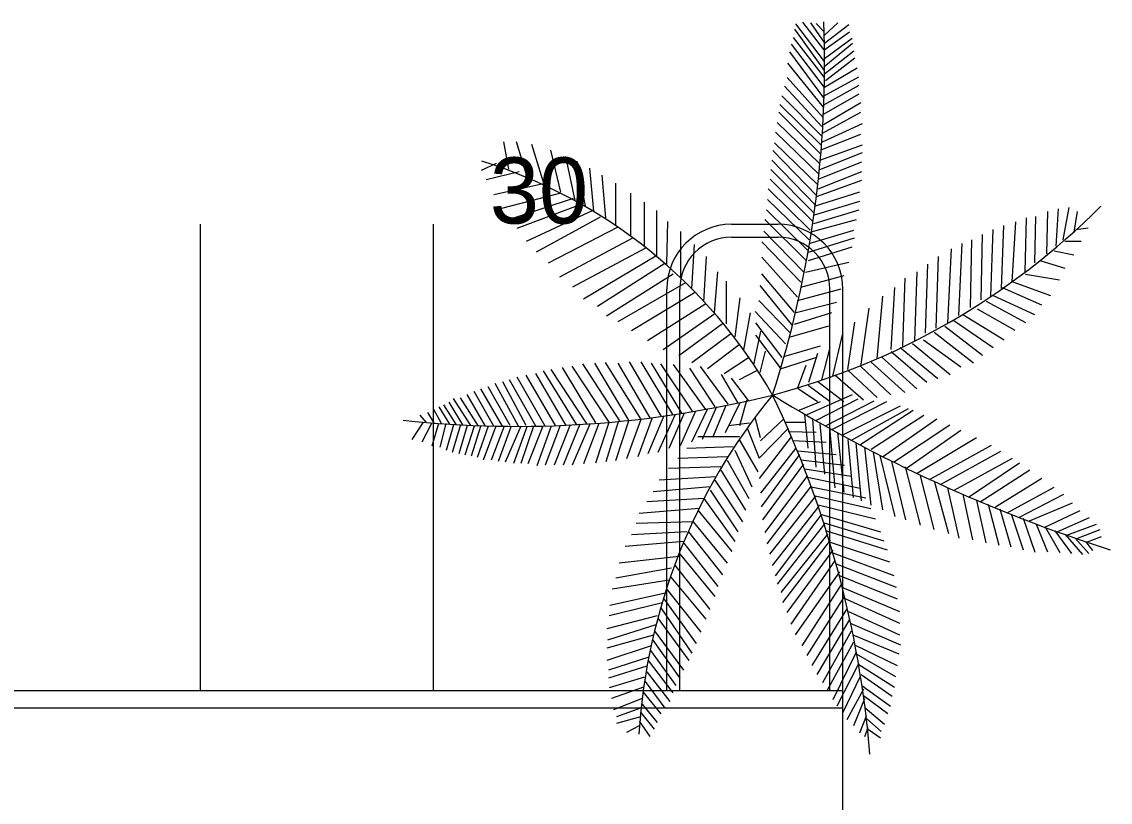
# Model space of a CAD drawing. Extents: x 6711323 to 6714641, y 1869258 to 1871224.
# Drawn here: x 6712869.21 to 6712911.22, y 1869741.77 to 1869771.88 of the extents above; entities that cross this region are included whole.
import ezdxf

# ---------------------------------------------------------------- set-up
doc = ezdxf.new("R2010")
doc.units = 0
for name, color, linetype in [('Curb Gutter (21)', 7, 'Continuous'), ('Exist Veg_Nat(4)', 7, 'Continuous'), ('Front Align (17)', 7, 'Continuous'), ('Ramp Anno (14)', 7, 'Continuous')]:
    doc.layers.add(name, color=color, linetype=linetype)

msp = doc.modelspace()

# ---------------------------------------------------------------- linework, layer by layer
at = {"layer": 'Curb Gutter (21)'}
for p, q in [((6712896.607, 1869764.072), (6712898.399, 1869764.072)), ((6712896.607, 1869763.572), (6712898.399, 1869763.572)), ((6712894.107, 1869746.072), (6712894.107, 1869761.572)), ((6712894.607, 1869746.072), (6712894.607, 1869761.572)), ((6712900.399, 1869746.097), (6712900.399, 1869761.572)), ((6712900.899, 1869712.572), (6712900.899, 1869761.572)), ((6712900.899, 1869746.072), (6712840.54, 1869746.072)), ((6712900.899, 1869745.406), (6712840.54, 1869745.406))]:
    msp.add_line(p, q, dxfattribs=at)
for centre, radius, start, end in [((6712896.607, 1869761.572), 2.5, 90, 180), ((6712898.399, 1869761.572), 2.5, 360, 90), ((6712896.607, 1869761.572), 2, 90, 180), ((6712898.399, 1869761.572), 2, 360, 90)]:
    msp.add_arc(centre, radius, start, end, dxfattribs=at)
at = {"layer": 'Exist Veg_Nat(4)'}
for p, q in [((6712900.192, 1869770.353), (6712899.084, 1869771.799)), ((6712900.171, 1869770.812), (6712899.361, 1869771.868)), ((6712900.192, 1869771.087), (6712899.659, 1869771.845)), ((6712900.149, 1869771.524), (6712899.873, 1869771.822)), ((6712900.192, 1869771.363), (6712900.703, 1869771.845)), ((6712900.192, 1869771.064), (6712901.129, 1869771.776)), ((6712900.192, 1869769.733), (6712898.999, 1869771.271)), ((6712900.192, 1869770.008), (6712899.042, 1869771.592)), ((6712900.171, 1869770.789), (6712901.151, 1869771.501)), ((6712900.192, 1869770.468), (6712901.257, 1869771.248)), ((6712900.192, 1869769.343), (6712898.914, 1869771.019)), ((6712900.171, 1869770.146), (6712901.278, 1869771.064)), ((6712900.171, 1869768.953), (6712898.85, 1869770.72)), ((6712900.192, 1869769.871), (6712901.321, 1869770.766)), ((6712900.235, 1869769.618), (6712901.364, 1869770.491)), ((6712900.153, 1869768.584), (6712898.779, 1869770.286)), ((6712900.192, 1869769.366), (6712901.449, 1869770.101)), ((6712900.118, 1869768.214), (6712898.745, 1869769.731)), ((6712900.128, 1869768.998), (6712901.513, 1869769.756)), ((6712900.084, 1869767.844), (6712898.642, 1869769.398)), ((6712900.171, 1869768.677), (6712901.534, 1869769.435)), ((6712900.084, 1869767.473), (6712898.539, 1869769.028)), ((6712900.153, 1869768.325), (6712901.526, 1869769.102)), ((6712900.153, 1869767.917), (6712901.595, 1869768.769)), ((6712900.05, 1869766.77), (6712898.436, 1869768.399)), ((6712900.05, 1869767.14), (6712898.47, 1869768.695)), ((6712900.118, 1869767.584), (6712901.595, 1869768.399)), ((6712900.015, 1869766.4), (6712898.367, 1869767.992)), ((6712900.118, 1869767.252), (6712901.664, 1869767.955)), ((6712899.981, 1869765.993), (6712898.298, 1869767.622)), ((6712900.084, 1869766.955), (6712901.595, 1869767.548)), ((6712888.015, 1869766.2), (6712887.82, 1869767.251)), ((6712888.698, 1869765.937), (6712888.307, 1869767.251)), ((6712889.381, 1869765.569), (6712888.893, 1869767.146)), ((6712899.947, 1869765.586), (6712898.264, 1869767.214)), ((6712900.015, 1869766.548), (6712901.664, 1869767.14)), ((6712890.015, 1869765.306), (6712889.625, 1869766.936)), ((6712890.57, 1869764.985), (6712890.212, 1869766.685)), ((6712899.878, 1869765.179), (6712898.195, 1869766.918)), ((6712900.015, 1869766.178), (6712901.664, 1869766.844)), ((6712887.527, 1869766.41), (6712886.941, 1869766.147)), ((6712890.963, 1869764.773), (6712890.641, 1869766.511)), ((6712891.284, 1869764.579), (6712891.141, 1869766.241)), ((6712899.844, 1869764.809), (6712898.161, 1869766.548)), ((6712899.947, 1869765.808), (6712901.629, 1869766.474)), ((6712888.405, 1869766.095), (6712887.137, 1869765.779)), ((6712891.749, 1869764.309), (6712891.606, 1869765.97)), ((6712899.741, 1869764.18), (6712898.092, 1869765.808)), ((6712899.775, 1869764.513), (6712898.127, 1869766.178)), ((6712899.947, 1869765.438), (6712901.629, 1869766.104)), ((6712889.283, 1869765.621), (6712887.429, 1869765.201)), ((6712892.142, 1869764.038), (6712892.142, 1869765.661)), ((6712899.638, 1869763.847), (6712898.024, 1869765.438)), ((6712899.878, 1869765.142), (6712901.629, 1869765.771)), ((6712889.966, 1869765.253), (6712887.722, 1869764.675)), ((6712890.498, 1869765.062), (6712888.032, 1869764.251)), ((6712892.714, 1869763.613), (6712892.714, 1869765.275)), ((6712899.603, 1869763.477), (6712897.989, 1869765.031)), ((6712899.809, 1869764.772), (6712901.561, 1869765.327)), ((6712899.809, 1869764.439), (6712901.561, 1869764.957)), ((6712890.784, 1869764.83), (6712888.318, 1869763.903)), ((6712891.249, 1869764.599), (6712888.676, 1869763.401)), ((6712893.25, 1869763.227), (6712893.25, 1869764.927)), ((6712893.715, 1869762.822), (6712893.715, 1869764.599)), ((6712899.535, 1869763.07), (6712897.955, 1869764.624)), ((6712899.775, 1869764.106), (6712901.526, 1869764.624)), ((6712908.767, 1869762.931), (6712908.812, 1869764.563)), ((6712909.134, 1869763.228), (6712909.226, 1869764.662)), ((6712909.409, 1869763.475), (6712909.639, 1869764.712)), ((6712909.822, 1869763.772), (6712909.96, 1869764.563)), ((6712891.535, 1869764.348), (6712889.069, 1869762.996)), ((6712894.108, 1869762.551), (6712894.144, 1869764.174)), ((6712899.5, 1869762.663), (6712897.887, 1869764.254)), ((6712899.672, 1869763.773), (6712901.423, 1869764.254)), ((6712907.436, 1869761.844), (6712907.574, 1869764.168)), ((6712907.941, 1869762.239), (6712907.987, 1869764.316)), ((6712908.308, 1869762.585), (6712908.354, 1869764.365)), ((6712892.214, 1869763.961), (6712889.533, 1869762.571)), ((6712894.644, 1869762.01), (6712894.644, 1869763.788)), ((6712899.397, 1869762.219), (6712897.852, 1869763.81)), ((6712899.603, 1869763.329), (6712901.32, 1869763.847)), ((6712906.61, 1869761.3), (6712906.702, 1869763.871)), ((6712907.023, 1869761.596), (6712907.115, 1869764.019)), ((6712909.886, 1869763.863), (6712910.37, 1869763.937)), ((6712892.786, 1869763.536), (6712889.962, 1869762.03)), ((6712895.073, 1869761.585), (6712895.18, 1869763.285)), ((6712899.275, 1869761.837), (6712897.775, 1869763.389)), ((6712899.569, 1869762.996), (6712901.355, 1869763.551)), ((6712905.371, 1869760.558), (6712905.509, 1869763.327)), ((6712905.83, 1869760.855), (6712905.876, 1869763.475)), ((6712906.243, 1869761.151), (6712906.289, 1869763.673)), ((6712909.471, 1869763.416), (6712910.093, 1869763.416)), ((6712893.286, 1869763.15), (6712890.463, 1869761.643)), ((6712893.679, 1869762.841), (6712890.891, 1869761.18)), ((6712899.575, 1869762.678), (6712901.255, 1869763.195)), ((6712904.958, 1869760.261), (6712905.096, 1869763.129)), ((6712909.056, 1869763.043), (6712909.817, 1869762.894)), ((6712891.428, 1869760.909), (6712894.036, 1869762.571)), ((6712895.537, 1869761.083), (6712895.644, 1869762.822)), ((6712899.155, 1869761.255), (6712897.775, 1869762.807)), ((6712899.455, 1869762.225), (6712901.135, 1869762.613)), ((6712904.086, 1869759.866), (6712904.178, 1869762.536)), ((6712904.499, 1869760.063), (6712904.591, 1869762.833)), ((6712908.503, 1869762.67), (6712909.471, 1869762.373)), ((6712891.785, 1869760.542), (6712894.358, 1869762.165)), ((6712895.947, 1869760.659), (6712896.079, 1869762.234)), ((6712899.035, 1869760.673), (6712897.775, 1869762.16)), ((6712899.275, 1869761.643), (6712900.955, 1869762.096)), ((6712903.673, 1869759.569), (6712903.765, 1869762.239)), ((6712907.95, 1869762.149), (6712909.263, 1869761.925)), ((6712894.822, 1869761.817), (6712892.214, 1869760.31)), ((6712896.41, 1869760.229), (6712896.41, 1869761.876)), ((6712898.975, 1869760.156), (6712897.715, 1869761.708)), ((6712899.155, 1869761.126), (6712900.835, 1869761.578)), ((6712902.764, 1869759.243), (6712902.902, 1869761.627)), ((6712903.215, 1869759.371), (6712903.306, 1869761.992)), ((6712907.051, 1869761.627), (6712908.572, 1869760.957)), ((6712907.465, 1869761.851), (6712908.918, 1869761.329)), ((6712895.18, 1869761.431), (6712892.749, 1869759.963)), ((6712896.742, 1869759.728), (6712896.941, 1869761.231)), ((6712902.23, 1869758.895), (6712902.441, 1869761.292)), ((6712906.705, 1869761.329), (6712908.295, 1869760.584)), ((6712895.609, 1869761.006), (6712893.357, 1869759.576)), ((6712898.855, 1869759.897), (6712897.655, 1869761.126)), ((6712899.095, 1869760.673), (6712900.655, 1869761.061)), ((6712901.596, 1869758.58), (6712901.913, 1869760.835)), ((6712906.083, 1869760.808), (6712907.535, 1869759.988)), ((6712906.429, 1869761.106), (6712907.95, 1869760.286)), ((6712895.966, 1869760.62), (6712893.965, 1869759.229)), ((6712897.073, 1869759.226), (6712897.338, 1869760.659)), ((6712898.681, 1869759.456), (6712897.521, 1869760.707)), ((6712899.035, 1869760.221), (6712900.475, 1869760.673)), ((6712905.184, 1869760.361), (6712906.705, 1869759.317)), ((6712905.53, 1869760.584), (6712907.12, 1869759.616)), ((6712896.252, 1869760.233), (6712894.572, 1869758.997)), ((6712897.471, 1869758.653), (6712897.735, 1869759.942)), ((6712898.562, 1869758.931), (6712897.545, 1869760.264)), ((6712898.875, 1869759.734), (6712900.358, 1869760.151)), ((6712901.094, 1869758.466), (6712901.358, 1869760.293)), ((6712904.423, 1869759.914), (6712905.945, 1869758.721)), ((6712904.838, 1869760.137), (6712906.29, 1869759.02)), ((6712896.573, 1869759.847), (6712895.073, 1869758.727)), ((6712898.5, 1869758.531), (6712897.545, 1869759.797)), ((6712900.513, 1869758.21), (6712900.883, 1869759.808)), ((6712904.008, 1869759.616), (6712905.46, 1869758.572)), ((6712896.895, 1869759.422), (6712895.68, 1869758.495)), ((6712897.709, 1869758.356), (6712897.918, 1869759.182)), ((6712898.617, 1869758.97), (6712900.036, 1869759.387)), ((6712899.583, 1869757.976), (6712899.929, 1869759.094)), ((6712900.091, 1869758.067), (6712900.408, 1869759.323)), ((6712902.764, 1869759.169), (6712904.147, 1869757.976)), ((6712903.109, 1869759.317), (6712904.562, 1869758.125)), ((6712903.594, 1869759.467), (6712905.046, 1869758.275)), ((6712892.292, 1869756.485), (6712890.866, 1869758.691)), ((6712892.638, 1869756.509), (6712891.326, 1869758.716)), ((6712893.098, 1869756.559), (6712891.74, 1869758.741)), ((6712893.466, 1869756.609), (6712892.223, 1869758.716)), ((6712893.903, 1869756.658), (6712892.661, 1869758.766)), ((6712894.34, 1869756.733), (6712893.121, 1869758.766)), ((6712894.685, 1869756.782), (6712893.512, 1869758.716)), ((6712895.1, 1869756.857), (6712893.88, 1869758.692)), ((6712895.606, 1869756.931), (6712894.363, 1869758.667)), ((6712897.253, 1869758.92), (6712896.323, 1869758.302)), ((6712898.5, 1869758.498), (6712899.856, 1869758.931)), ((6712901.992, 1869758.752), (6712903.286, 1869757.582)), ((6712902.388, 1869758.952), (6712903.761, 1869757.724)), ((6712889.807, 1869756.311), (6712888.68, 1869758.245)), ((6712890.221, 1869756.311), (6712889.048, 1869758.319)), ((6712890.635, 1869756.336), (6712889.347, 1869758.419)), ((6712891.027, 1869756.361), (6712889.646, 1869758.468)), ((6712891.372, 1869756.41), (6712890.083, 1869758.543)), ((6712891.878, 1869756.435), (6712890.451, 1869758.592)), ((6712895.974, 1869757.03), (6712894.992, 1869758.515)), ((6712896.48, 1869757.129), (6712895.408, 1869758.59)), ((6712896.841, 1869757.192), (6712896.215, 1869758.281)), ((6712897.574, 1869758.417), (6712896.895, 1869758.07)), ((6712899.147, 1869757.732), (6712899.486, 1869758.631)), ((6712900.593, 1869758.267), (6712901.702, 1869757.296)), ((6712901.094, 1869758.438), (6712902.23, 1869757.382)), ((6712901.596, 1869758.58), (6712902.758, 1869757.496)), ((6712888.058, 1869756.311), (6712887.207, 1869757.799)), ((6712888.38, 1869756.286), (6712887.483, 1869757.923)), ((6712888.68, 1869756.311), (6712887.782, 1869757.997)), ((6712889.048, 1869756.286), (6712888.035, 1869758.071)), ((6712889.416, 1869756.286), (6712888.334, 1869758.171)), ((6712897.257, 1869757.267), (6712896.598, 1869758.131)), ((6712899.563, 1869757.867), (6712900.408, 1869757.239)), ((6712899.933, 1869758.01), (6712900.936, 1869757.239)), ((6712886.839, 1869756.286), (6712886.148, 1869757.377)), ((6712887.115, 1869756.286), (6712886.401, 1869757.501)), ((6712887.437, 1869756.286), (6712886.677, 1869757.625)), ((6712887.759, 1869756.286), (6712886.931, 1869757.724)), ((6712899.178, 1869757.732), (6712899.918, 1869757.232)), ((6712899.517, 1869756.732), (6712901.274, 1869757.499)), ((6712885.734, 1869756.36), (6712885.32, 1869757.03)), ((6712885.987, 1869756.335), (6712885.504, 1869757.104)), ((6712886.24, 1869756.335), (6712885.711, 1869757.203)), ((6712886.539, 1869756.311), (6712885.872, 1869757.352)), ((6712895.675, 1869756.956), (6712895.054, 1869755.667)), ((6712896.02, 1869757.03), (6712895.468, 1869755.766)), ((6712896.388, 1869757.08), (6712895.894, 1869755.9)), ((6712896.91, 1869757.154), (6712896.354, 1869756.027)), ((6712897.188, 1869757.267), (6712896.91, 1869756.29)), ((6712899.209, 1869756.899), (6712900.041, 1869757.232)), ((6712899.856, 1869756.499), (6712901.489, 1869757.332)), ((6712900.226, 1869756.3), (6712902.105, 1869757.265)), ((6712900.503, 1869756.166), (6712902.599, 1869757.232)), ((6712900.873, 1869755.933), (6712903.123, 1869757.066)), ((6712901.212, 1869755.733), (6712903.431, 1869756.966)), ((6712884.814, 1869756.435), (6712884.584, 1869756.707)), ((6712885.136, 1869756.385), (6712884.883, 1869756.806)), ((6712885.412, 1869756.385), (6712885.113, 1869756.931)), ((6712893.098, 1869756.534), (6712892.546, 1869755.022)), ((6712893.535, 1869756.609), (6712892.983, 1869755.096)), ((6712893.995, 1869756.683), (6712893.374, 1869755.22)), ((6712894.432, 1869756.733), (6712893.765, 1869755.27)), ((6712894.778, 1869756.782), (6712894.179, 1869755.419)), ((6712895.215, 1869756.857), (6712894.617, 1869755.518)), ((6712897.501, 1869756.629), (6712897.709, 1869755.84)), ((6712898.628, 1869756.569), (6712897.724, 1869755.715)), ((6712899.425, 1869756.732), (6712899.548, 1869755.433)), ((6712899.733, 1869756.566), (6712899.856, 1869754.7)), ((6712901.551, 1869755.567), (6712903.615, 1869756.899)), ((6712901.991, 1869755.393), (6712904.031, 1869756.701)), ((6712902.425, 1869755.095), (6712904.528, 1869756.565)), ((6712884.698, 1869756.435), (6712884.261, 1869755.765)), ((6712885.021, 1869756.385), (6712884.653, 1869755.666)), ((6712885.297, 1869756.385), (6712885.044, 1869755.517)), ((6712885.573, 1869756.385), (6712885.343, 1869755.467)), ((6712885.872, 1869756.335), (6712885.596, 1869755.344)), ((6712886.148, 1869756.335), (6712885.826, 1869755.269)), ((6712886.401, 1869756.311), (6712886.079, 1869755.22)), ((6712886.677, 1869756.286), (6712886.309, 1869755.17)), ((6712886.931, 1869756.311), (6712886.562, 1869755.121)), ((6712887.207, 1869756.286), (6712886.793, 1869755.071)), ((6712887.506, 1869756.286), (6712887.023, 1869754.972)), ((6712887.828, 1869756.286), (6712887.322, 1869754.972)), ((6712888.104, 1869756.286), (6712887.598, 1869754.922)), ((6712888.473, 1869756.286), (6712887.874, 1869754.898)), ((6712888.703, 1869756.261), (6712888.196, 1869754.848)), ((6712888.956, 1869756.286), (6712888.473, 1869754.848)), ((6712889.324, 1869756.286), (6712888.749, 1869754.823)), ((6712889.646, 1869756.286), (6712889.094, 1869754.749)), ((6712889.991, 1869756.311), (6712889.416, 1869754.773)), ((6712890.382, 1869756.336), (6712889.761, 1869754.773)), ((6712890.75, 1869756.361), (6712890.106, 1869754.774)), ((6712891.141, 1869756.361), (6712890.451, 1869754.774)), ((6712891.487, 1869756.385), (6712890.889, 1869754.823)), ((6712891.372, 1869754.873), (6712891.878, 1869756.435)), ((6712891.763, 1869754.923), (6712892.246, 1869756.46)), ((6712892.638, 1869756.509), (6712892.131, 1869754.947)), ((6712897.292, 1869756.403), (6712896.493, 1869756.29)), ((6712897.223, 1869756.178), (6712897.674, 1869755.051)), ((6712898.798, 1869756.203), (6712897.667, 1869755.045)), ((6712898.685, 1869756.437), (6712899.454, 1869756.437)), ((6712900.01, 1869756.366), (6712900.195, 1869754.434)), ((6712900.38, 1869756.233), (6712900.596, 1869753.901)), ((6712902.855, 1869754.891), (6712905.03, 1869756.335)), ((6712903.356, 1869754.661), (6712905.46, 1869756.131)), ((6712896.908, 1869755.87), (6712895.301, 1869755.87)), ((6712896.908, 1869755.741), (6712897.623, 1869754.522)), ((6712898.905, 1869755.872), (6712897.667, 1869754.267)), ((6712898.794, 1869756.08), (6712899.867, 1869756.051)), ((6712898.959, 1869755.723), (6712900.252, 1869755.664)), ((6712900.688, 1869756.033), (6712900.935, 1869753.734)), ((6712901.089, 1869755.766), (6712901.304, 1869753.535)), ((6712903.739, 1869754.46), (6712906.057, 1869755.851)), ((6712896.67, 1869755.485), (6712894.884, 1869755.421)), ((6712896.73, 1869755.356), (6712897.385, 1869753.945)), ((6712899.07, 1869755.426), (6712897.722, 1869753.701)), ((6712899.152, 1869755.337), (6712900.638, 1869755.188)), ((6712901.397, 1869755.633), (6712901.613, 1869753.401)), ((6712901.736, 1869755.467), (6712901.982, 1869753.235)), ((6712902.066, 1869755.273), (6712902.43, 1869753.053)), ((6712904.24, 1869754.229), (6712906.631, 1869755.548)), ((6712904.67, 1869754.026), (6712906.992, 1869755.323)), ((6712896.432, 1869755.1), (6712894.527, 1869755.035)), ((6712896.432, 1869754.971), (6712897.266, 1869753.495)), ((6712899.221, 1869755.188), (6712897.75, 1869753.165)), ((6712899.29, 1869754.98), (6712900.968, 1869754.772)), ((6712902.329, 1869755.146), (6712902.909, 1869752.801)), ((6712902.783, 1869754.917), (6712903.313, 1869752.669)), ((6712905.194, 1869753.818), (6712907.448, 1869755.048)), ((6712905.744, 1869753.54), (6712907.712, 1869754.874)), ((6712896.194, 1869754.715), (6712894.17, 1869754.65)), ((6712896.194, 1869754.586), (6712897.147, 1869753.046)), ((6712899.381, 1869754.812), (6712897.804, 1869752.674)), ((6712899.434, 1869754.639), (6712901.226, 1869754.35)), ((6712903.307, 1869754.71), (6712903.884, 1869752.46)), ((6712906.197, 1869753.359), (6712908.121, 1869754.601)), ((6712896.016, 1869754.329), (6712893.812, 1869754.201)), ((6712895.956, 1869754.201), (6712897.028, 1869752.597)), ((6712899.542, 1869754.378), (6712897.884, 1869752.183)), ((6712899.542, 1869754.321), (6712901.573, 1869753.887)), ((6712903.883, 1869754.36), (6712904.406, 1869752.299)), ((6712904.43, 1869754.176), (6712904.975, 1869752.137)), ((6712906.79, 1869753.172), (6712908.579, 1869754.279)), ((6712895.777, 1869753.945), (6712893.574, 1869753.752)), ((6712895.777, 1869753.816), (6712896.849, 1869752.212)), ((6712899.648, 1869753.945), (6712897.964, 1869751.749)), ((6712899.675, 1869753.945), (6712901.787, 1869753.512)), ((6712899.836, 1869753.598), (6712901.974, 1869753.107)), ((6712904.933, 1869753.899), (6712905.381, 1869751.958)), ((6712905.528, 1869753.665), (6712905.9, 1869751.891)), ((6712907.245, 1869752.944), (6712909.062, 1869753.932)), ((6712907.697, 1869752.763), (6712909.424, 1869753.66)), ((6712895.539, 1869753.495), (6712893.336, 1869753.367)), ((6712895.539, 1869753.495), (6712896.73, 1869751.827)), ((6712899.836, 1869753.569), (6712898.071, 1869751.345)), ((6712899.969, 1869753.194), (6712898.178, 1869750.911)), ((6712899.942, 1869753.252), (6712902.161, 1869752.702)), ((6712906.054, 1869753.411), (6712906.42, 1869751.778)), ((6712906.505, 1869753.277), (6712906.916, 1869751.689)), ((6712908.101, 1869752.631), (6712909.765, 1869753.319)), ((6712895.36, 1869753.11), (6712893.038, 1869752.918)), ((6712895.301, 1869753.046), (6712896.611, 1869751.442)), ((6712900.049, 1869752.847), (6712898.285, 1869750.506)), ((6712900.076, 1869752.876), (6712902.348, 1869752.211)), ((6712906.957, 1869753.096), (6712907.388, 1869751.625)), ((6712907.412, 1869752.868), (6712907.861, 1869751.513)), ((6712908.674, 1869752.374), (6712910.057, 1869753.027)), ((6712909.196, 1869752.214), (6712910.419, 1869752.755)), ((6712895.122, 1869752.597), (6712892.919, 1869752.533)), ((6712895.122, 1869752.597), (6712896.432, 1869750.993)), ((6712900.21, 1869752.529), (6712898.365, 1869750.189)), ((6712900.183, 1869752.558), (6712902.482, 1869751.864)), ((6712907.863, 1869752.733), (6712908.31, 1869751.426)), ((6712908.364, 1869752.504), (6712908.803, 1869751.431)), ((6712908.721, 1869752.373), (6712909.273, 1869751.413)), ((6712909.547, 1869752.076), (6712910.686, 1869752.507)), ((6712894.884, 1869752.212), (6712892.741, 1869752.084)), ((6712894.943, 1869752.212), (6712896.254, 1869750.544)), ((6712900.317, 1869752.125), (6712898.506, 1869749.864)), ((6712900.263, 1869752.24), (6712902.616, 1869751.518)), ((6712909.078, 1869752.242), (6712909.72, 1869751.373)), ((6712909.474, 1869752.103), (6712910.147, 1869751.336)), ((6712909.868, 1869751.967), (6712910.388, 1869751.376)), ((6712909.929, 1869751.952), (6712910.828, 1869752.295)), ((6712910.347, 1869751.815), (6712910.887, 1869752.026)), ((6712894.765, 1869751.827), (6712892.503, 1869751.635)), ((6712894.765, 1869751.763), (6712896.075, 1869750.095)), ((6712900.411, 1869751.882), (6712898.571, 1869749.482)), ((6712900.508, 1869751.5), (6712898.732, 1869749.099)), ((6712900.411, 1869751.812), (6712902.703, 1869751.047)), ((6712910.262, 1869751.83), (6712910.53, 1869751.492)), ((6712894.586, 1869751.25), (6712892.264, 1869750.993)), ((6712894.586, 1869751.378), (6712895.956, 1869749.71)), ((6712900.604, 1869751.117), (6712898.893, 1869748.647)), ((6712900.508, 1869751.395), (6712902.864, 1869750.525)), ((6712894.289, 1869750.801), (6712892.145, 1869750.416)), ((6712894.401, 1869750.93), (6712895.762, 1869749.214)), ((6712900.766, 1869750.664), (6712899.055, 1869748.229)), ((6712900.637, 1869750.977), (6712902.961, 1869750.073)), ((6712894.198, 1869750.337), (6712891.997, 1869749.994)), ((6712894.256, 1869750.462), (6712895.617, 1869748.839)), ((6712900.766, 1869750.525), (6712902.993, 1869749.621)), ((6712894.053, 1869749.838), (6712891.91, 1869749.37)), ((6712894.082, 1869750.025), (6712895.414, 1869748.34)), ((6712900.863, 1869750.212), (6712899.313, 1869747.812)), ((6712900.863, 1869750.073), (6712903.09, 1869749.134)), ((6712893.937, 1869749.464), (6712891.881, 1869748.964)), ((6712893.995, 1869749.619), (6712895.24, 1869747.903)), ((6712900.959, 1869749.725), (6712899.507, 1869747.429)), ((6712900.927, 1869749.656), (6712903.09, 1869748.681)), ((6712893.879, 1869749.276), (6712895.067, 1869747.529)), ((6712901.056, 1869749.238), (6712899.7, 1869747.046)), ((6712901.121, 1869749.134), (6712903.09, 1869748.229)), ((6712893.735, 1869748.964), (6712891.794, 1869748.465)), ((6712893.677, 1869748.621), (6712891.823, 1869748.028)), ((6712893.763, 1869748.871), (6712894.951, 1869747.248)), ((6712901.153, 1869748.821), (6712899.894, 1869746.698)), ((6712901.186, 1869748.681), (6712903.123, 1869747.846)), ((6712893.59, 1869748.215), (6712891.794, 1869747.716)), ((6712893.619, 1869748.403), (6712894.748, 1869746.873)), ((6712901.218, 1869748.368), (6712900.12, 1869746.385)), ((6712901.282, 1869748.229), (6712903.058, 1869747.499)), ((6712893.503, 1869747.809), (6712891.794, 1869747.248)), ((6712893.561, 1869748.028), (6712894.603, 1869746.561)), ((6712901.315, 1869747.951), (6712900.282, 1869746.072)), ((6712901.347, 1869747.846), (6712902.993, 1869747.046)), ((6712893.416, 1869747.373), (6712891.852, 1869746.873)), ((6712893.474, 1869747.622), (6712894.459, 1869746.281)), ((6712901.411, 1869747.568), (6712900.508, 1869745.724)), ((6712901.411, 1869747.499), (6712902.929, 1869746.629)), ((6712893.329, 1869747.029), (6712891.852, 1869746.561)), ((6712893.387, 1869747.248), (6712894.343, 1869746)), ((6712901.508, 1869747.116), (6712900.669, 1869745.481)), ((6712901.476, 1869747.116), (6712902.897, 1869746.211)), ((6712893.242, 1869746.593), (6712891.881, 1869746.187)), ((6712893.329, 1869746.811), (6712894.227, 1869745.656)), ((6712901.573, 1869746.629), (6712900.895, 1869745.237)), ((6712901.605, 1869746.698), (6712902.8, 1869745.864)), ((6712893.213, 1869746.218), (6712891.968, 1869745.781)), ((6712893.271, 1869746.436), (6712894.024, 1869745.407)), ((6712901.702, 1869746.142), (6712901.056, 1869744.959)), ((6712901.637, 1869746.281), (6712902.735, 1869745.481)), ((6712893.155, 1869745.781), (6712892.055, 1869745.344)), ((6712893.184, 1869746.031), (6712893.879, 1869745.188)), ((6712901.734, 1869745.759), (6712901.315, 1869744.716)), ((6712901.702, 1869745.898), (6712902.638, 1869745.203)), ((6712893.097, 1869745.407), (6712892.171, 1869745.064)), ((6712893.097, 1869745.251), (6712893.619, 1869744.595)), ((6712893.155, 1869745.563), (6712893.735, 1869744.845)), ((6712901.767, 1869745.411), (6712902.509, 1869744.785)), ((6712893.097, 1869745.064), (6712892.171, 1869744.814)), ((6712893.039, 1869744.907), (6712893.445, 1869744.315)), ((6712901.799, 1869745.098), (6712901.541, 1869744.437)), ((6712901.831, 1869744.994), (6712902.38, 1869744.507)), ((6712893.039, 1869744.72), (6712892.547, 1869744.471)), ((6712901.863, 1869744.646), (6712901.734, 1869744.298)), ((6712901.896, 1869744.576), (6712902.348, 1869744.263))]:
    msp.add_line(p, q, dxfattribs=at)
for centre, radius, start, end in [((6712858.691, 1869770.249), 41.505, 342.0895, 2.2566), ((6712881.134, 1869747.761), 19.628, 29.6945, 72.7086), ((6712891.074, 1869784.525), 27.96, 284.733, 315.0526), ((6712888.312, 1869797.178), 40.903, 263.8592, 283.9671), ((6712915.734, 1869743.015), 22.745, 140.4934, 176.4992), ((6712929.353, 1869808.314), 59.624, 238.48348, 252.29429), ((6712862.698, 1869740.408), 39.381, 4.7, 25.6971)]:
    msp.add_arc(centre, radius, start, end, dxfattribs=at)
at = {"layer": 'Front Align (17)'}
for p, q in [((6712876.107, 1869746.072), (6712876.107, 1869764.072)), ((6712885.107, 1869746.072), (6712885.107, 1869764.072))]:
    msp.add_line(p, q, dxfattribs=at)

# ---------------------------------------------------------------- texts
at = {"layer": 'Ramp Anno (14)'}
msp.add_text('30', height=2.55, dxfattribs=at).set_placement((6712887.277, 1869764.099))

doc.saveas('drawing.dxf')
